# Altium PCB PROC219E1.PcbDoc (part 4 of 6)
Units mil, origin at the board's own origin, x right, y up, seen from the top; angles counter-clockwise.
Board outline 5354.33 x 5354.33 mil, 4 copper layers (Top Layer, Inner Layer 1, Inner Layer 2, Bottom Layer), stack 62.449 mil thick; 579 components, 299 nets, 1709 pads, 802 vias.
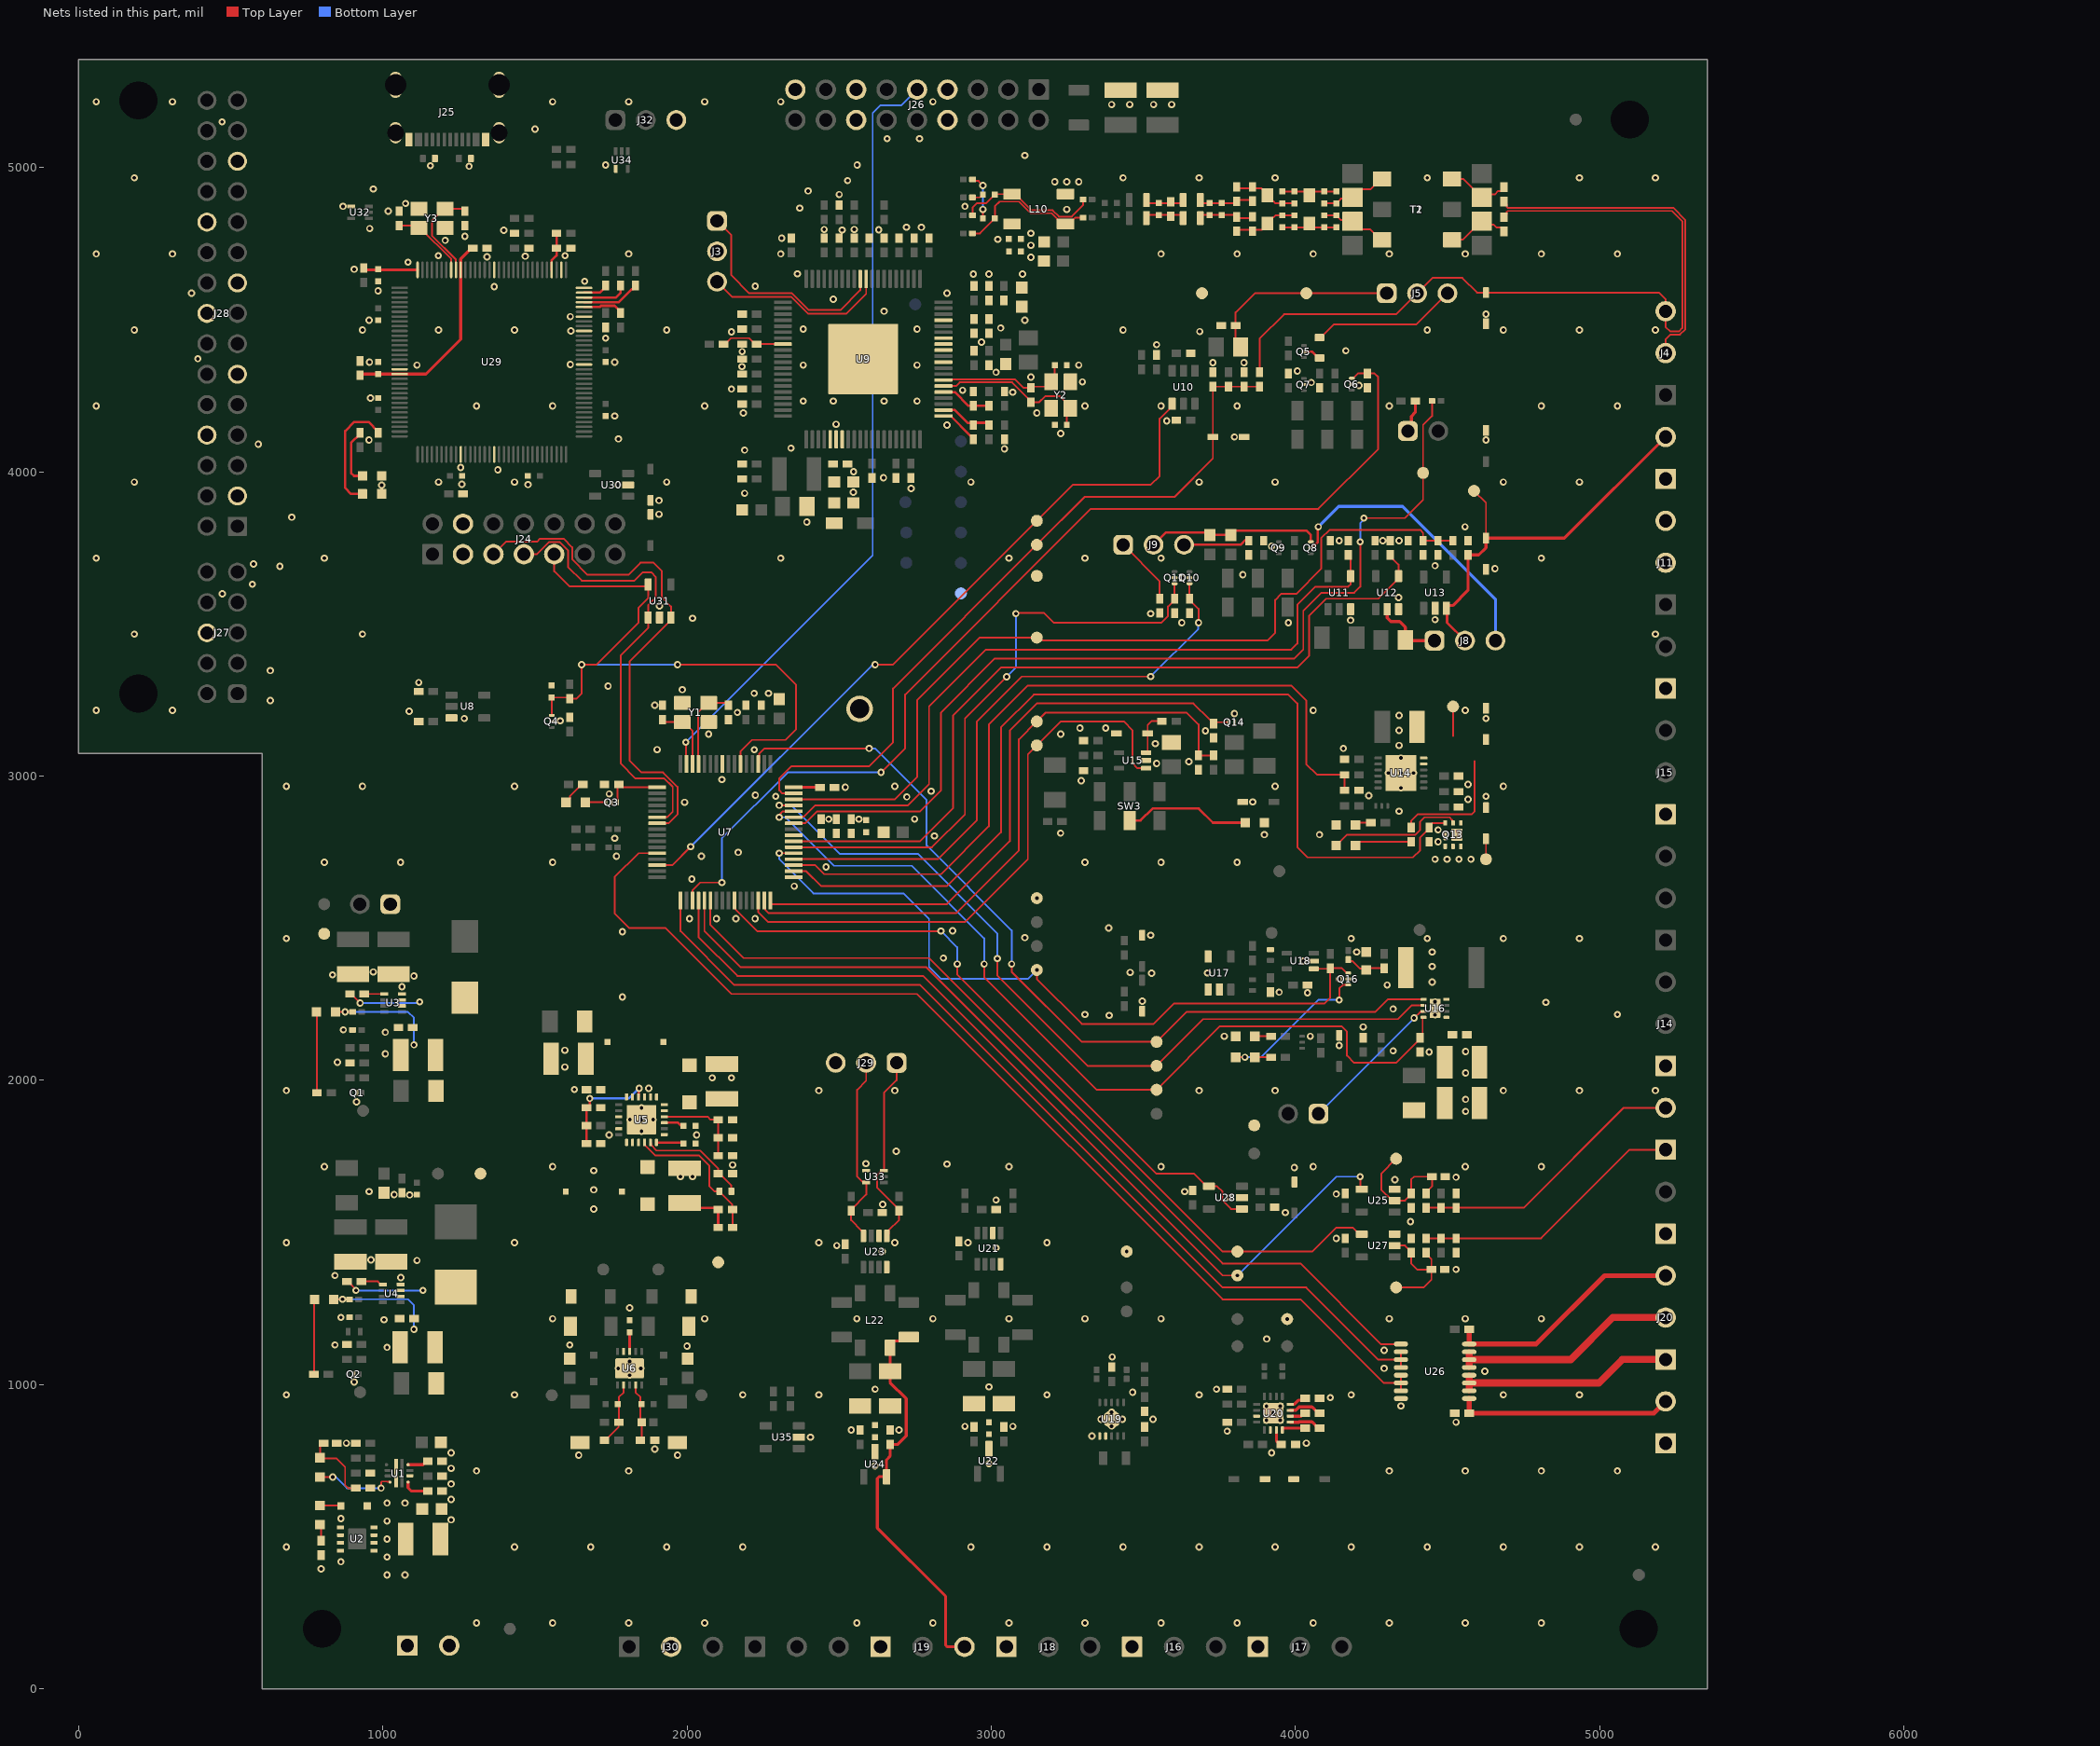
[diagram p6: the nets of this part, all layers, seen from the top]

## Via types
v1: diameter 23.62, hole 11.81, Top Layer to Bottom Layer, tented both sides, 802 vias

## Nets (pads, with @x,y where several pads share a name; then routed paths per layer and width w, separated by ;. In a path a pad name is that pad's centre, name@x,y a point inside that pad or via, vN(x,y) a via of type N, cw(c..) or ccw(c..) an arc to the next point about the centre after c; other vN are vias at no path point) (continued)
CAN2_P: C141.1 J19.3 L22.4 R139.2 R142.2 U24.2 | length 1306.5
  Top Layer w9.84: R139.2@2728.35,1155.51 2715.55,1142.72 2680.12,1142.72 2667.32,1129.92 L22.4@2667.32,1121.06 R142.2@2667.32,1043.31 2667.32,1006.43 2720.47,953.28 2720.47,830.71 2692.91,803.15 C141.1@2667.32,803.15 2667.32,764.27 2655.51,752.46 U24.2@2655.51,696.85 2630.8,696.85 2625.03,691.08 2625.03,528.54 2849.83,303.73 2849.83,143.56 2855.6,137.8 J19.3@2911.81,137.8
CAN2_RX: J29.2 R141.1 U23.4 U33.5 | length 637.1
  Top Layer w5.91: U23.4@2579.72,1488.19 2579.72,1500 2573.82,1505.91 2573.27,1505.91 2539.37,1539.81 2539.37,1574.8 2588.98,1624.41 U33.5@2588.98,1663.39 2586.02,1666.34 2575.79,1666.34 2559.06,1683.07 2559.06,1968.5 2588.58,1998.03 J29.2@2588.58,2057.09
CAN2_TX: J29.1 R140.1 U23.1 U33.3 | length 647.1
  Top Layer w5.91: U23.1@2656.5,1488.19 2662.4,1494.09 2662.4,1506.17 2696.85,1540.62 2696.85,1574.8 2624.31,1647.34 2624.31,1688.07 2636.04,1699.8 2644.29,1699.8 U33.3@2647.24,1702.76 2647.24,1958.27 2688.5,1999.52 2688.5,2057 J29.1@2688.58,2057.09
ChargeSeq1: D19.2 J11.3 R96.1 TP25.1 U14.5 U14.6 | length 505.2
  Top Layer w5.91: R96.1@4379.92,2830.71 4379.92,2852.36 4401.57,2874.02 4578.74,2874.02 4588.58,2883.86 4588.58,3049.21 ; 4517.72,3131.89 TP25.1@4517.72,3228.35
ChargeSeq2: D21.2 D22.1 J11.2 Q13.1 Q13.2 Q13.5 Q13.6 Q13.8 TP26.1 | length 517
  Top Layer w5.91: D22.1@4133.86,2771.65 4168.62,2806.41 4393.02,2806.41 4409.45,2822.84 4409.45,2850.39 4423.17,2864.11 4505.97,2864.11 4514.76,2855.31 4514.76,2848.43 Q13.2@4517.72,2845.47 ; TP26.1@4625.98,2726.38 D21.2@4625.98,2793.31
CP_EV: D17.2 J5.3 | length 481.2
  Top Layer w5.91: D17.2@4078.74,4440.94 4082.68,4440.94 4125.98,4484.25 4397.24,4484.25 J5.3@4499.61,4586.61
CP_N: C97.1 J4.2 NT1.2 | length 1112.7
  Top Layer w5.91: C97.1@4685.04,4887.8 4693.9,4878.94 4693.9,4870.62 4697.36,4867.16 5241.34,4867.16 5281.56,4826.94 5281.56,4468.34 5263.95,4450.72 5232.28,4450.72 5216.54,4434.98 J4.2@5216.54,4386.32
CP_P: C107.1 D14.2 J4.3 J5.2 R63.2 | length 2678.4
  Top Layer w5.91: R63.2@3881.89,4326.77 3881.89,4437.01 3962.6,4517.72 4330.71,4517.72 J5.2@4399.61,4586.61 4449.8,4636.81 4548.23,4636.81 4596.46,4588.58 D14.2@4625.98,4588.58 5194.88,4588.58 5216.54,4566.93 5216.54,4524.11 5216.54,4476.38 5232.28,4460.63 5259.84,4460.63 5271.65,4472.44 5271.65,4822.83 5237.24,4857.25 4697.36,4857.25 4693.9,4853.79 4693.9,4845.47 C107.1@4685.04,4836.61
DEBUG_ID4: R154.1 U29.63 | length 83
  Top Layer w7.87: U29.63@1661.42,4588.58 1712.6,4588.58 1732.28,4608.27 R154.1@1732.28,4612.2
DEBUG_ID5: R155.1 U29.62 | length 150.7
  Top Layer w7.87: U29.62@1661.42,4572.83 1766.5,4572.83 1781.5,4587.83 R155.1@1781.5,4612.2
DEBUG_ID6: R156.1 U29.61 | length 194.4
  Top Layer w7.87: U29.61@1661.42,4557.09 1712.14,4557.09 1712.27,4557.21 1775.72,4557.21 1818.9,4600.39 1822.83,4600.39 1830.71,4608.27 R156.1@1830.71,4612.2
DEBUG_ID7: R157.1 U29.60 | length 133.9
  Top Layer w7.87: U29.60@1661.42,4541.34 1713.18,4541.34 1717.18,4545.34 1761.75,4545.34 1781.5,4525.59 R157.1@1781.5,4521.65
DIG_IN_1: J21.2 R145.2 R146.1 R147.2 | length 923.6
  Top Layer w5.91: R146.1@4429.13,1580.71 R145.2@4478.35,1580.71 R147.2@4527.56,1580.71 4750,1580.71 5078.74,1909.45 J21.2@5216.54,1909.45
DIG_IN_2: J21.1 R149.2 R150.1 R151.2 | length 908.1
  Top Layer w5.91: R150.1@4429.13,1480.31 R151.2@4527.56,1480.32 4807.09,1480.32 5097.93,1771.16 5216.04,1771.16 J21.1@5216.54,1771.65
DIG_OUT_1: J20.3 R148.1 U26.16 | length 787.1
  Top Layer w15.75: R148.1@4570.87,1181.1 U26.16@4570.87,1132.87 4791.05,1132.87 5015.96,1357.78 J20.3@5216.54,1357.78
DIG_OUT_2: J20.2 U26.13 U26.14 U26.15 | length 746.3
  Top Layer w23.62: U26.13@4570.87,1060.04 U26.14@4570.87,1081.69 ; U26.15@4570.87,1103.35 U26.14@4570.87,1081.69 ; J20.2@5216.54,1219.98 5042.81,1219.98 4904.53,1081.69 U26.14@4570.87,1081.69
DIG_OUT_3: J20.1 U26.10 U26.11 U26.12 | length 721
  Top Layer w23.62: U26.10@4570.87,983.27 U26.11@4570.87,1004.92 ; U26.12@4570.87,1026.57 U26.11@4570.87,1004.92 ; J20.1@5216.54,1082.18 5074.31,1082.18 4997.05,1004.92 U26.11@4570.87,1004.92
DIG_OUT_COM: C145.1 J23.2 U26.9 | length 710.5
  Top Layer w15.75: U26.9@4571.24,953.36 U26.9@4570.87,953.74 C145.1@4570.87,905.51 5177.66,905.51 J23.2@5216.54,944.39
EN_RSTD: R43.1 R48.2 U9.8 | length 211.2
  Top Layer w5.91: R43.1@2120.08,4419.29 2124.02,4419.29 2143.7,4438.98 2204.72,4438.98 2224.41,4419.29 R48.2@2228.35,4419.29 U9.8@2314.96,4419.29
GBT_CC1: D18.1 J7.2 J8.2 R77.1 TP23.1 U13.3 | length 1343.2
  Top Layer w5.91: TP23.1@4586.61,3937.01 4625.98,3897.64 D18.1@4625.98,3781.5
  Top Layer w7.87: U13.3@4502.95,3560.18 4498.03,3555.26 4498.03,3503.94 J8.2@4557.09,3444.88
  Top Layer w9.84: U13.3@4502.95,3560.18 4516.87,3560.18 4566.93,3610.24 R77.1@4566.93,3726.38 4602.36,3726.38 4625.98,3750 D18.1@4625.98,3781.5 4883.86,3781.5 J7.2@5216.54,4114.17
GBT_EV: J8.3 Q8.2@4050.42,3750 | length 954.2
  Top Layer w7.87: Q8.2@4050.42,3750 4055.15,3750 4073.38,3768.23 4073.38,3817.47 v1(4074.8,3818.9)
  Bottom Layer w9.84: v1(4074.8,3818.9) 4141.73,3885.83 4352.36,3885.83 4657.09,3581.1 J8.3@4657.09,3444.88
GND: C1.2 C2.1 C3.1 C4.1 C5.2 C6.2 C7.2 C9.1 C10.2 C11.1 C12.1 C14.1 C15.2 C16.1 C17.1 C18.2 C19.2 C20.2 C21.1 C22.2 C25.1 C26.2 C27.1 C28.1 C29.2 C31.2 C32.2 C33.2 C34.2 C35.1 C37.1 C38.1 C39.2 C40.2 C41.2 C42.2 C43.1 C44.2 C45.1 C46.2 C47.2 C48.1 C49.2 C50.2 C51.2 C54.1 C55.2 C56.2 C57.2 C58.2 C59.1 C60.2 C61.2 C62.2 C63.2 C64.2 C65.2 C66.2 C67.2 C68.2 C69.2 C70.2 C71.2 C72.2 C73.2 C74.2 C75.2 C76.2 C77.2 C78.2 C79.2 C80.2 C81.2 C82.2 C83.2 C84.2 C86.2 C87.2 C88.1 C89.1 C90.1 C91.2 C92.1 C93.1 C114.1 C115.1 C116.2 C117.1 C118.2 C119.1 C120.2 C121.1 C122.1 C123.2 C124.1 C125.2 C126.1 C127.2 C128.2 C129.2 C132.2 C133.2 C134.2 C135.2 C136.2 C137.2 C138.1 C139.2 C140.2 C141.2 C142.2 C143.1 C144.1 C145.2 C146.1 C147.2 C148.2 C149.2 C150.1 C151.1 C152.1 C153.1 C154.1 C155.1 C156.2 C157.2 C158.1 C159.2 C160.1 C161.2 C162.1 C163.2 C164.2 D1.2 D14.1 D15.2 D16.2 D18.2 D19.1 D20.1 D21.1 D23.1 D24.2 D25.1 D26.2 D27.1 D29.2 D30.2 D31.1 D32.1 D33.2 D34.2 D35.2 D36.2 D37.2 D38.1 D39.1 J1.2 J2.1 J3.2 J7.1 J10.1 J14.1 J15.1 J16.1 J17.1 J18.1 J19.1 J22.1 J23.1 J24.3 J24.4 J25.1 J25.2 J25.3 J25.4 J25.A1-B12 J25.B1-A12 J26.7 J26.8 J26.13 J26.14 J26.17 J27.6 J28.3 J28.8 J28.11 J28.16 J28.17 J28.22 J28.25 J29.3 J30.2 J32.3 L8.2 NT1.1 Q1.2@915.35,1958.66 Q2.2@905.51,1033.46 Q3.2@1751.97,2913.39 Q4.2@1555.12,3179.13 Q6.2@4185.04,4287.4 Q7.2@4027.56,4286.42 Q9.2@3944.88,3750 Q10.2@3651.57,3651.57 Q11.2@3602.36,3651.57 Q13.4 Q13.7 Q14.2@3799.21,3176.68 Q16.2@4173.23,2332.68 R5.1 R6.1 R7.2 R11.2 R12.1 R17.2 R18.1 R22.2 R23.2 R30.1 R36.2 R38.1 R39.1 R40.2 R47.1 R48.1 R49.1 R50.1 R59.1 R62.1 R65.1 R68.1 R71.2 R72.2 R75.1 R76.1 R77.2 R79.1 R83.1 R84.1 R85.2 R86.2 R87.2 R89.1 R90.2 R92.1 R93.1 R95.1 R100.1 R101.2 R105.1 R106.1 R110.2 R112.2 R115.1 R116.2 R127.1 R132.2 R147.1 R151.1 R153.1 R162.1 R163.1 R165.1 R166.1 TP18.1 TP37.1 TP38.1 TP41.1 TP44.1 TP45.1 TP49.1 TP50.1 TP51.1 TP52.1 TP58.1 U1.8 U2.5 U2.6 U2.7 U2.8 U3.4 U4.4 U5.2 U5.3 U5.9 U5.11 U5.19 U5.25@1850.24,1870.27 U6.4 U6.11 U7.17 U7.41 U8.3 U9.54 U9.81 U11.3 U12.3 U13.2 U14.13 U15.2 U16.4 U16.9 U17.1 U17.2 U17.5 U18.2 U19.6 U19.7 U19.11 U20.11 U20.14 U20.17 U21.2 U21.8 U22.3 U23.2 U23.8 U24.3 U25.3 U26.8 U27.3 U28.2 U29.10 U29.17 U29.48 U29.55 U29.58 U29.64 U29.66 U29.80 U29.114 U30.2 U31.2 U32.4 U33.4 U34.4 U35.2 Y1.2 Y1.4 Y2.2 Y2.4 Y3.2 Y3.4
  other v1: 1308,216 1558,216 1808,216 2058,216 2558,216 2808,216 3058,216 3308,216 3558,216 3808,216 4058,216 4308,216 4558,216 4808,216 797.24,393.7 862.2,417.32 683,466 1433,466 1683,466 1933,466 2183,466 2933,466 3183,466 3433,466 3683,466 3933,466 4183,466 4433,466 4683,466 4933,466 5183,466 1224.41,555.12 862.2,559.06 1224.41,622.05 1224.41,673.23 1308,716 1808,716 4308,716 4558,716 4808,716 5058,716 1224.41,724.41 2618.11,732.28 2992.13,740.16 1643.7,767.72 1968.5,767.72 1224.41,775.59 3921.26,775.59 1893.7,787.4 880.11,807.1 4035.43,807.09 2405.51,826.77 3330.71,830.71 3775.59,846.46 2539.37,850.39 2696.85,850.39 2913.39,862.2 3070.87,862.2 3395.67,863.19 4527.56,875.98 3904.33,882.68 3950,882.68 3360.24,885.83 3431.1,885.83 3531.5,885.83 3927.17,905.51 3395.67,908.46 3904.33,928.35 3950,928.35 4346.46,929.13 4114.17,956.69 683,966 1433,966 2183,966 2433,966 3183,966 3683,966 4183,966 4683,966 4933,966 3464.57,974.41 2618.11,984.25 3740.16,984.25 2992.13,992.13 905.51,1007.87 1811.02,1030.51 4622.05,1043.31 1773.62,1053.15 1848.43,1053.15 4291.34,1053.15 1811.02,1075.79 3397.64,1090.55 4291.34,1112.2 1013.78,1122.05 2000,1125.98 842.52,1129.92 1614.17,1129.92 3905.51,1149.61 1003.94,1212.6 3972.44,1215.07 1558,1216 2058,1216 2558,1216 2808,1216 3058,1216 3308,1216 3558,1216 4308,1216 4558,1216 4808,1216 862.2,1220.47 1811.02,1251.97 1059.06,1351.38 842.52,1358.27 4527.56,1377.95 1112.2,1407.48 960.63,1409.45 2641.73,1437.01 3444.88,1437.01 3015.75,1448.82 2492.13,1456.69 683,1466 1433,1466 2433,1466 2683,1466 3183,1466 2923.23,1466.54 4133.86,1480.32 4377.95,1535.43 3966.54,1564.96 1692.91,1576.77 2642.88,1592.01 3015.75,1606.3 3783.46,1614.17 1088.32,1622.93 1036.98,1623.77 4133.86,1625.98 954.72,1633.86 3635.8,1634 1692.91,1639.76 4326.77,1673.23 4527.56,1681.1 1978.35,1683.07 2017.72,1683.07 1692.91,1702.76 3996.06,1712.6 808,1716 1558,1716 3058,1716 3558,1716 4058,1716 4558,1716 4808,1716 2149.45,1721.65 2854.33,1724.41 2587.66,1726.07 2687.19,1766.81 1743.94,1820.07 2031.34,1820.07 1850.24,1831.88 1811.85,1870.27 1850.24,1870.27 1888.63,1870.27 4559.06,1897.64 1850.24,1908.66 913.39,1929.13 4559.06,1937.01 683,1966 2433,1966 2683,1966 3683,1966 3933,1966 4683,1966 4933,1966 5183,1966 1629.77,1969.68 1873.86,1973.62 2082.68,2007.87 2145.67,2007.87 4559.06,2023.62 1598.43,2043.31 850.39,2059.06 1007.87,2086.61 4438.98,2092.52 4559.06,2094.49 4320.87,2096.46 1598.43,2098.43 4143.7,2114.27 3765.94,2144.47 4048.31,2144.47 1007.87,2157.48 870.08,2165.35 4222.44,2175.2 3387.8,2212.98 4458.66,2214.57 3308,2216 5058,2216 4320.87,2234.25 4822.83,2255.91 4458.66,2257.87 3496.06,2259.84 1787.3,2273.83 4039.37,2287.4 3946.22,2289.37 1062.99,2307.09 4301.18,2312.99 4448.82,2322.83 4143.7,2332.68 1102.36,2342.52 834.65,2346.46 3526.95,2351.74 3710.63,2352.36 3456.69,2354.33 968.81,2355.9 4448.82,2374.02 4025.59,2391.73 2842.52,2401.57 4200.79,2421.26 4448.82,2421.26 683,2466 4183,2466 4433,2466 4683,2466 4933,2466 3110.24,2468.5 3523.62,2476.38 1787.3,2488.19 2873.04,2490.99 3385.83,2500 2007.87,2530.85 2096.45,2530.85 2160.46,2530.85 2223.66,2530.85 3149.61,2598.43 2352.36,2637.8 2015.75,2661.42 2456.69,2700.79 808,2716 1058,2716 1558,2716 3308,2716 3558,2716 3808,2716 4458.66,2726.38 4498.03,2726.38 4537.4,2726.38 4576.77,2726.38 1767.72,2736.22 2047.24,2736.22 2168.37,2748.8 4468.5,2783.46 1761.81,2795.28 2813.3,2802.81 3897.64,2807.09 4078.74,2807.09 3227.81,2812.26 4468.5,2822.83 2465.59,2858.01 2564.93,2858.01 2748.03,2858.27 4340.55,2883.86 1992.13,2913.39 3859.07,2914.55 4566.93,2923.23 2722.09,2931.27 2291.34,2933.07 4625.98,2933.07 4240.63,2935.44 2224.41,2937.01 1744.09,2940.94 2802.13,2950 4346.46,2960.63 2519.89,2962.81 683,2966 933,2966 1433,2966 2683,2966 3933,2966 4683,2966 4566.93,2972.44 3295.28,2984.25 2114.17,2988.19 4305.12,3009.84 4346.46,3009.84 4387.8,3009.84 3543.31,3041.34 3649.61,3047.24 4346.46,3059.06 2220.87,3086.43 1901.57,3086.61 4157.48,3090.55 4340.55,3100.39 3539.37,3106.3 2070.87,3137.8 3228.35,3137.8 3703.84,3148.46 4340.55,3149.61 3291.34,3157.48 3376.11,3157.48 1582.68,3181.1 1267.72,3188.98 4625.98,3188.98 4340.55,3198.82 3799.21,3204.72 2165.35,3208.66 1086.61,3212.6 58,3216 308,3216 4058,3216 4558,3216 1893.7,3232.28 629.92,3248.03 2220.47,3271.65 2267.72,3271.65 1984.25,3283.46 1740.16,3295.28 1118.11,3307.09 629.92,3346.46 183,3466 933,3466 5183,3466 3625.98,3503.94 3976.38,3503.94 4181.1,3511.81 4458.66,3513.78 2018.09,3518.38 3523.62,3533.46 1909.45,3559.06 4338.58,3586.61 472.29,3598.71 570.87,3629.92 3626.97,3651.57 3826.77,3661.42 4655.51,3681.1 661.42,3688.98 4458.66,3690.94 574.8,3696.85 58,3716 808,3716 2308,3716 3058,3716 3308,3716 3558,3716 4808,3716 3921.1,3755 4143.7,3773.62 4286.45,3773.62 4340.55,3773.62 4557.09,3818.9 2393.7,3834.65 700.79,3850.39 1907.48,3860.24 1907.48,3905.51 2188.98,3929.13 2546.75,3932.58 2736.22,3944.88 996.1,3955.56 1771.65,3956.69 1477.37,3957.69 1259.84,3958.66 183,3966 1183,3966 1433,3966 1933,3966 2933,3966 3683,3966 3933,3966 4683,3966 4933,3966 2645.67,3980.31 2547.24,4000 1377.95,4005.91 1255.91,4013.59 2188.98,4070.87 3043.31,4074.8 2341.57,4077.2 590.55,4090.55 954.37,4104.01 4625.98,4104.33 1774.16,4107.71 3799.21,4114.17 3228.35,4125.98 2854.33,4153.54 2489.87,4155.98 3576.75,4167.07 1761.81,4183.07 2185.04,4192.91 3149.61,4192.91 58,4216 1308,4216 1558,4216 2058,4216 3308,4216 3558,4216 3808,4216 4308,4216 4808,4216 5058,4216 2381.89,4232.28 2480.32,4232.28 2647.64,4232.28 2755.91,4232.28 959.69,4241.97 3070.67,4261.15 2905.51,4267.72 2145.67,4271.65 4208.66,4283.46 4051.81,4293.17 3299.21,4295.28 3129.92,4311.02 3015.75,4326.77 4005.91,4330.71 2180.5,4345.44 1112.2,4350.39 2381.89,4350.39 2755.91,4350.39 3287.4,4350.39 1616.14,4352.36 3728.35,4358.27 3830.71,4358.27 955.78,4360.23 1761.81,4360.24 391.76,4371.16 2181.1,4394.89 4165.35,4397.64 3543.31,4417.32 2967.74,4426.17 1732.28,4438.98 2145.67,4459.57 3685.04,4460.63 1618.11,4462.6 183,4466 933,4466 1183,4466 1433,4466 1933,4466 3433,4466 4433,4466 4683,4466 4933,4466 5183,4466 2381.89,4468.5 2755.91,4468.5 3031,4472.35 954.73,4498.03 3110.24,4498.03 1616.14,4509.84 4625.98,4517.72 2647.64,4527.56 2480.32,4566.93 370.79,4587.06 2854.33,4586.61 984.25,4594.49 1366.14,4608.27 2224.05,4609.91 1663.39,4625.98 2362.84,4650.16 2940.94,4649.61 2992.13,4649.61 3102.36,4649.61 905.51,4665.35 1082.48,4688.49 1342.52,4706.2 1467.69,4708.14 1182.29,4710.28 1598.83,4710.18 58,4716 308,4716 1808,4716 2308,4716 3558,4716 3808,4716 4058,4716 4308,4716 4558,4716 4808,4716 5058,4716 1204.94,4760.24 3021.65,4763.78 2311.02,4767.72 1269.68,4773.62 1397.64,4793.31 2509.76,4794.45 2629.92,4795.28 2450.87,4796.18 2549.37,4796.18 956.69,4799.21 2721.17,4803.43 2769.95,4803.22 1017.72,4856.3 3248.03,4862.2 2370.08,4866.14 868.73,4872.18 2913.39,4872.05 1074.8,4881.89 2500,4911.18 2397.6,4922.68 968.84,4929.02 2527.56,4956.69 183,4966 3433,4966 3683,4966 3933,4966 4433,4966 4933,4966 5183,4966 1283.46,5003.94 1156.38,5005.64 1732.28,5007.87 2559.06,5007.87 3110.24,5039.37 2657.48,5094.49 2763.78,5094.49 1500,5125.98 471.29,5149.64 3395.67,5206.69 3454.72,5206.69 3533.46,5206.69 3592.52,5206.69 58,5216 308,5216 1558,5216 1808,5216 2058,5216 2308,5216 2808,5216
HFXIN: C43.2 U7.45 Y1.1 | length 286.6
  Top Layer w5.91: U7.45@2037.4,3039.37 2036.35,3040.42 2036.35,3210.57 2065.95,3240.16 Y1.1@2070.87,3240.16 2127.95,3240.16 C43.2@2135.83,3232.28
HFXOUT: C44.1 U7.46 Y1.3 | length 222.8
  Top Layer w5.91: C44.1@1919.29,3185.04 1927.17,3177.17 Y1.3@1984.25,3177.17 1989.17,3177.17 2017.72,3148.62 U7.46@2017.72,3039.37
MSP_ADC_CP: C93.2 D15.1 R63.1 R64.1 R65.2 TP21.1 U7.31 | length 2450.4
  Top Layer w5.91: U7.31@2350.39,2942.91 2312.99,2942.91 2303.15,2952.76 2303.15,2992.13 2342.52,3031.5 2598.43,3031.5 2677.17,3110.24 2677.17,3287.4 TP21.1@3149.61,3759.84 3307.09,3917.32 3602.36,3917.32 3728.35,4043.31 D15.1@3728.35,4114.17 C93.2@3728.35,4279.53 R64.1@3779.53,4279.53 R63.1@3881.89,4279.53 R63.1@3885.82,4283.46
MSP_ADC_GBT_DP1: C117.2 R78.1 R79.2 TP24.1 U7.30 | length 2841.9
  Top Layer w5.91: U7.30@2350.39,2923.23 2683.07,2923.23 2755.91,2996.06 2755.91,3248.03 2962.6,3454.72 3158.66,3454.72 3168.5,3444.88 3907.48,3444.88 3933.08,3470.48 3933.08,3578.75 3952.73,3598.4 4001.94,3598.4 4084.27,3680.72 4084.27,3781.11 4112.21,3809.06 4409.45,3809.06 4419.29,3799.21 C117.2@4419.29,3773.62 R79.2@4468.5,3773.62 R78.1@4517.72,3773.62
MSP_ADC_IN_3: U7.10 U28.1 U28.4 | length 2172.4
  Top Layer w5.91: U7.10@2155.51,2590.55 2158.46,2587.6 2158.46,2562.01 2230.31,2490.16 v1(2834.65,2490.16) ; v1(2887.8,2381.89) 2887.8,2348.43 3543.31,1692.91 3666.34,1692.91 3707.68,1651.57 3742.13,1651.57 3759.84,1633.86 3759.84,1604.33 3787.4,1576.77 U28.1@3823.82,1576.77
  Bottom Layer w5.91: v1(2834.65,2490.16) 2887.8,2437.01 v1(2887.8,2381.89)
MSP_ADC_PP: R67.2 TP22.1 U7.26 | length 3196.1
  Top Layer w5.91: U7.26@2350.39,2844.49 2387.8,2844.49 2427.17,2883.86 2765.75,2883.86 2834.65,2952.76 2834.65,3208.66 3011.81,3385.83 3996.06,3385.83 4025.59,3415.35 4025.59,3543.31 4084.65,3602.36 4192.91,3602.36 4212.6,3622.05 v1(4212.6,3769.69) ; v1(4224.74,3847.59) 4359.4,3847.59 4419.29,3907.48 TP22.1@4419.29,3996.06 4419.29,4153.54 4448.72,4182.97 R67.2@4448.72,4232.28
  Bottom Layer w5.91: v1(4212.6,3769.69) 4212.6,3830.66 4224.74,3842.79 v1(4224.74,3847.59)
MSP_DEBUG_UART_RX: J24.5 U7.55 U31.3 | length 1728.1
  Top Layer w5.91: J24.5@1363.39,3728.74 1404.79,3770.14 1506.36,3770.14 1515.75,3779.53 1594.49,3779.53 1622.45,3751.57 1622.45,3712.2 1673.23,3661.42 1807.09,3661.42 1846.46,3700.79 1889.76,3700.79 1917.32,3673.23 1917.32,3586.61 1946.85,3557.09 U31.3@1946.85,3520.67 1937.99,3511.81 1937.99,3503.33 1811.02,3376.37 1811.02,3051.18 1850.39,3011.81 1920.99,3011.81 1968.5,2964.3 1968.5,2874.02 1938.98,2844.49 U7.55@1901.57,2844.49
MSP_DEBUG_UART_TX: J24.7 U7.54 U31.1 | length 1557.8
  Top Layer w5.91: J24.7@1463.39,3728.74 1506.23,3728.74 1546.64,3769.16 1580.13,3769.16 1609.47,3739.82 1609.47,3685.81 1653.54,3641.73 1826.77,3641.73 1854.33,3669.29 1881.89,3669.29 1897.52,3653.66 1897.52,3586.5 1872.05,3561.02 U31.1@1872.05,3520.67 1872.05,3486.22 1781.5,3395.67 1781.5,3041.34 1830.82,2992.02 1925.2,2992.02 1952.76,2964.46 1952.76,2881.89 1935.81,2864.94 1902.35,2864.94 U7.54@1901.57,2864.17
MSP_GPIO_CdM_d1: R88.1 R90.1 U7.19 | length 2571
  Top Layer w5.91: U7.19@2350.39,2706.69 2421.26,2706.69 2450.79,2677.17 2834.65,2677.17 2992.13,2834.65 2992.13,3169.29 3120.08,3297.24 3986.22,3297.24 4035.43,3248.03 4035.43,3039.37 4070.87,3003.94 R88.1@4161.42,3003.94 R90.1@4161.42,2952.76
MSP_GPIO_CdM_d2: Q13.3 R95.2 U7.18 | length 3199.4
  Top Layer w5.91: U7.18@2350.39,2687.01 2391.73,2687.01 2440.94,2637.8 2854.33,2637.8 3031.5,2814.96 3031.5,3159.45 3139.76,3267.72 3976.38,3267.72 4005.91,3238.19 4005.91,2765.75 4039.37,2732.28 4385.83,2732.28 4409.45,2755.91 4409.45,2797.86 4429.51,2817.91 4430.12,2817.91 4438.98,2826.77 4438.98,2834.65 4449.8,2845.47 Q13.3@4492.13,2845.47
MSP_GPIO_CdM_EV_CP: Q14.1@3779.53,3176.68 R101.1 U7.16 | length 2033.8
  Top Layer w5.91: U7.16@2273.62,2590.55 2273.62,2581.69 2276.57,2578.74 2854.33,2578.74 3061.02,2785.43 3061.02,3149.61 3149.61,3238.19 3664.55,3238.19 3717.52,3185.22 3721.46,3185.22 3730.31,3176.36 R101.1@3730.31,3172.43 3734.57,3176.68 Q14.1@3779.53,3176.68
MSP_GPIO_CdM_j: R99.2 R100.2 TP27.1 U7.15 | length 2113.7
  Top Layer w5.91: U7.15@2253.94,2590.55 2256.89,2587.6 2256.89,2560.6 2268.28,2549.21 2883.86,2549.21 3090.55,2755.91 3090.55,3120.08 TP27.1@3149.61,3179.13 3179.13,3208.66 3641.73,3208.66 3681.1,3169.29 R100.2@3681.1,3067.69 R99.2@3730.31,3067.69
MSP_GPIO_CdM_PD: TP28.1 U7.14 U15.1 | length 1928.4
  Top Layer w5.91: U7.14@2234.25,2590.55 2234.25,2552.17 2266.73,2519.68 2913.39,2519.68 3120.08,2726.38 3120.08,3070.87 TP28.1@3149.61,3100.39 3228.35,3179.13 3435.04,3179.13 3464.57,3149.61 3464.57,3041.34 3480.31,3025.59 U15.1@3508.86,3025.59
MSP_GPIO_EV_Charge: Q6.1@4185.04,4307.09 R71.1 U7.3 | length 3411.7
  Top Layer w5.91: U7.3@2017.72,2590.55 2018.49,2591.32 2018.49,2624.79 2043.31,2649.61 v1(2114.17,2649.61) ; v1(2637.8,3011.81) 2716.54,3090.55 2716.54,3267.72 3326.77,3877.95 4074.8,3877.95 4271.65,4074.8 4271.65,4311.02 4259.84,4322.83 R71.1@4236.22,4322.83 4205.51,4322.83 4189.76,4307.09 Q6.1@4185.04,4307.09
  Bottom Layer w5.91: v1(2114.17,2649.61) 2114.17,2795.28 2330.71,3011.81 v1(2637.8,3011.81)
MSP_GPIO_GBT_EV_S2: Q10.1@3651.57,3631.89 R86.1 U7.20 | length 1994.8
  Top Layer w5.91: U7.20@2350.39,2726.38 2824.8,2726.38 2952.76,2854.33 2952.76,3179.13 3100.39,3326.77 v1(3523.62,3326.77) ; Q10.1@3651.57,3631.89 3651.57,3578.74 3681.1,3549.21 v1(3681.1,3503.94)
  Bottom Layer w5.91: v1(3523.62,3326.77) 3680.12,3483.27 3680.12,3502.95 v1(3681.1,3503.94)
MSP_GPIO_GBT_EV_S2': Q11.1@3602.36,3631.89 R85.1 U7.22 | length 1974.8
  Top Layer w5.91: U7.22@2350.39,2765.75 2805.12,2765.75 2913.39,2874.02 2913.39,3188.98 v1@3050.1,3325.69 ; v1@3050.18,3325.6 v1(3050.18,3325.77) ; v1(3080.71,3533.46) 3082.68,3535.43 3173.23,3535.43 3204.72,3503.94 3559.12,3503.94 3580.82,3525.64 3580.82,3557.2 3602.36,3578.74 R85.1@3602.36,3582.68 Q11.1@3602.36,3631.89
  Bottom Layer w5.91: v1(3050.18,3325.77) 3080.71,3356.3 v1(3080.71,3533.46)
MSP_GPIO_GBT_S0: R75.2 U7.27 U11.4 | length 2472.5
  Top Layer w5.91: U7.27@2350.39,2864.17 2352.15,2865.93 2383.65,2865.93 2421.26,2903.54 2726.38,2903.54 2795.28,2972.44 2795.28,3228.35 2982.28,3415.35 3986.22,3415.35 4005.91,3435.04 4005.91,3562.99 4064.96,3622.05 4173.23,3622.05 4181.1,3629.92 U11.4@4181.1,3656.5 4181.1,3718.5 R75.2@4173.23,3726.38
MSP_GPIO_GBT_S1: R76.2 U7.23 U12.4 | length 2690.8
  Top Layer w5.91: U7.23@2350.39,2785.43 2765.75,2785.43 2874.02,2893.7 2874.02,3198.82 3031.5,3356.3 4005.91,3356.3 4045.28,3395.67 4045.28,3527.36 4100.6,3582.68 4272.64,3582.68 4338.58,3648.62 U12.4@4338.58,3656.5 4338.58,3694.88 4311.02,3722.44 R76.2@4311.02,3726.38
MSP_GPIO_PL_CdM_FB: Q16.1@4173.23,2352.36 R119.2 TP35.1 U7.21 U18.1 | length 2489.1
  Top Layer w5.91: v1(2303.15,2746.06) U7.21@2350.39,2746.06 ; v1(3149.61,2362.2) 3149.61,2332.68 3297.24,2185.04 3533.46,2185.04 3600.39,2251.97 4094.49,2251.97 4114.17,2271.65 R119.2@4114.17,2368.11 ; U18.1@4060.04,2366.14 4112.2,2366.14 R119.2@4114.17,2368.11 ; Q16.1@4173.23,2352.36 4168.5,2352.36 4152.76,2368.11 R119.2@4114.17,2368.11
  Bottom Layer w5.91: v1(2303.15,2746.06) 2303.15,2726.38 2415.35,2614.17 2710.63,2614.17 2795.28,2529.53 2795.28,2372.05 2834.65,2332.68 3120.08,2332.68 v1(3149.61,2362.2)
MSP_GPIO_PL_DIR: TP33.1 U7.29 U16.6 | length 2683.1
  Top Layer w5.91: v1(2303.15,2903.54) U7.29@2350.39,2903.54 ; v1(3019.69,2400.13) 3019.69,2344.49 3316.93,2047.24 TP33.1@3543.31,2047.24 3696.85,2200.79 4336.61,2200.79 4381.89,2246.06 U16.6@4421.26,2246.06
  Bottom Layer w5.91: v1(2303.15,2903.54) 2342.52,2903.54 2501.97,2744.09 2757.87,2744.09 3019.69,2482.28 v1(3019.69,2400.13)
MSP_GPIO_PL_nSLEEP: R110.1 TP31.1 U7.28 U16.8 | length 2903.8
  Top Layer w5.91: v1(2303.15,2864.17) 2306.54,2867.56 2306.54,2875.6 2314.79,2883.86 U7.28@2350.39,2883.86 ; v1(2976.38,2381.89) 2976.38,2338.58 3346.46,1968.5 TP31.1@3543.31,1968.5 3751.97,2177.17 4151.39,2177.17 4169.06,2159.5 4169.06,2080.94 4192.91,2057.09 4330.71,2057.09 4409.45,2135.83 R110.1@4409.45,2139.76 4417.74,2148.05 4417.74,2204.72 4419.7,2206.69 U16.8@4421.26,2206.69
  Bottom Layer w5.91: v1(2303.15,2864.17) 2322.83,2864.17 2482.28,2704.72 2738.19,2704.72 2976.38,2466.54 v1(2976.38,2381.89)
MSP_IO_IN_1: TP54.1 U7.4 U25.4 | length 2933.9
  Top Layer w5.91: U7.4@2037.4,2590.55 2037.4,2470.47 2165.35,2342.52 2775.59,2342.52 3759.84,1358.27 v1(3809.06,1358.27) ; v1(4212.6,1683.07) 4212.6,1646.65 U25.4@4217.52,1641.73
  Bottom Layer w5.91: v1(3809.06,1358.27) 4133.86,1683.07 v1(4212.6,1683.07)
MSP_IO_IN_2: TP56.1 U7.6 U27.4 | length 2707.8
  Top Layer w5.91: U7.6@2076.77,2590.55 2076.33,2590.11 2076.33,2510.28 2185.04,2401.57 2795.28,2401.57 3759.84,1437.01 TP56.1@3809.06,1437.01 4055.12,1437.01 4133.86,1515.75 4187.99,1515.75 4209.65,1494.09 U27.4@4217.52,1494.09
MSP_IO_OUT_1: U7.5 U26.1 | length 2952
  Top Layer w5.91: U7.5@2057.09,2590.55 2057.09,2490.16 2175.2,2372.05 2785.43,2372.05 3759.84,1397.64 4015.75,1397.64 4280.51,1132.87 U26.1@4346.46,1132.87
MSP_IO_OUT_2: U7.1 U26.2 U26.3 U26.4 | length 3103.1
  Top Layer w5.91: U7.1@1978.35,2590.55 1978.35,2490.16 2155.51,2312.99 2765.75,2312.99 3759.84,1318.9 4035.43,1318.9 4272.64,1081.69 U26.3@4346.46,1081.69 ; U26.4@4346.46,1056.1 U26.3@4346.46,1081.69 ; U26.2@4346.46,1107.28 U26.3@4346.46,1081.69
MSP_IO_OUT_3: U7.60 U26.5 U26.6 U26.7 | length 3566
  Top Layer w5.91: U7.60@1901.57,2746.06 1840.55,2746.06 1761.81,2667.32 1761.81,2549.21 1811.02,2500 1929.13,2500 2145.67,2283.46 2755.91,2283.46 3759.84,1279.53 4015.75,1279.53 4290.35,1004.92 U26.6@4346.46,1004.92 ; U26.7@4346.46,979.33 U26.6@4346.46,1004.92 ; U26.5@4346.46,1030.51 U26.6@4346.46,1004.92
MSP_LED: Q3.1@1771.65,2913.39 R36.1 U7.49 | length 190.7
  Top Layer w5.91: Q3.1@1771.65,2913.39 1771.65,2968.5 R36.1@1775.59,2972.44 1779.53,2972.44 1789.37,2962.6 U7.49@1901.57,2962.6
MSP_PWM_CP: TP20.1 U7.62 U10.4 | length 2435.9
  Top Layer w5.91: U7.62@1901.57,2706.69 1950.79,2706.69 v1(2011.81,2767.72) ; v1(2618.11,3366.14) 2677.17,3366.14 TP20.1@3149.61,3838.58 3267.72,3956.69 3523.62,3956.69 3553.15,3986.22 3553.15,4174.21 3594.49,4215.55 U10.4@3594.49,4223.43
  Bottom Layer w5.91: v1(2011.81,2767.72) 2606.85,3362.75 2614.72,3362.75 v1(2618.11,3366.14)
MSP_PWM_PL_EN: TP32.1 U7.35 U16.5 | length 2850.8
  Top Layer w5.91: U7.35@2234.25,3039.37 2236.39,3041.51 2236.39,3072.24 2254.71,3090.55 v1(2598.43,3090.55) ; v1(3066.93,2381.89) 3066.93,2356.3 3297.24,2125.98 TP32.1@3543.31,2125.98 3641.73,2224.41 4261.81,2224.41 4303.15,2265.75 U16.5@4421.26,2265.75
  Bottom Layer w5.91: v1(2598.43,3090.55) 2618.11,3090.55 2787.4,2921.26 2787.4,2771.65 3066.93,2492.13 v1(3066.93,2381.89)
MSP_PWM_R_ENABLE: J26.9 U7.47 | length 2572.7
  Top Layer w5.91: v1(1995.79,3110.94) 1996.91,3109.82 1996.91,3040.49 U7.47@1998.03,3039.37
  Bottom Layer w5.91: v1(1995.79,3110.94) 2610.05,3725.21 2610.05,5178.95 2635.6,5204.49 2704.49,5204.49 J26.9@2755.91,5255.91
MSP_R\S\T\: C49.1 J24.9 Q4.3@1555.12,3198.82 R37.1 U7.38 U31.5 | length 2158.9
  Top Layer w5.91: Q4.3@1555.12,3198.82 C49.1@1555.12,3257.87 1610.24,3257.87 R37.1@1614.17,3253.94 1635.83,3253.94 1653.54,3271.65 v1(1653.54,3366.14) 1702.76,3366.14 1840.55,3503.94 1840.55,3553.15 1872.05,3584.65 U31.5@1872.05,3628.94 ; J24.9@1563.39,3728.74 1563.39,3672.83 1612.72,3623.5 U31.5@1870.08,3623.5 ; v1(1968.5,3366.14) 2291.34,3366.14 2358.35,3299.13 2358.35,3153.62 2323.25,3118.52 2213.01,3118.52 2175.2,3080.71 U7.38@2175.2,3039.37
  Bottom Layer w5.91: v1(1653.54,3366.14) v1(1968.5,3366.14)
NetC4_2: C4.2 C5.1 D3.1 J1.1 R1.2 R2.2 U1.5 U2.1 U2.2 U2.3 U2.4
  other v1: 1013.78,374.02 1072.83,374.02 1013.78,433.07 1013.78,492.13 1013.78,551.18 1013.78,610.24 1072.83,610.24
NetC6_1: C6.1 U1.10 | length 69.9
  Top Layer w9.84: U1.10@1082.68,736.22 1131.89,736.22 1143.7,748.03 C6.1@1147.64,748.03
NetC7_1: C7.1 U1.7 | length 88.1
  Top Layer w9.84: U1.7@1082.68,679.13 1082.71,660.4 1093.5,649.61 C7.1@1147.64,649.61
NetC8_1: C8.1 U3.5 | length 65.4
  Top Layer w5.91: C8.1@938.98,2283.46 U3.5@1004.33,2283.46
NetC8_2: C8.2 L2.1 U3.3 | length 243.2
  Top Layer w5.91: C8.2@891.73,2283.46 895.67,2283.46 v1(925.2,2253.94)
  Bottom Layer w5.91: v1(925.2,2253.94) 1112.65,2253.94 1116.38,2257.67 v1(1121.17,2257.67)
NetC9_2: C9.2 C10.1 D5.2 L1.2 R8.2 U3.2 | length 379.2
  Top Layer w5.91: D5.2@844.49,2224.41 v1(875.98,2224.41) R8.2@900.54,2224.41
  Bottom Layer w5.91: v1(875.98,2224.41) 1054.73,2224.41 1054.81,2224.49 1071.18,2224.49 1071.26,2224.41 1082.68,2224.41 1102.36,2204.72 v1(1102.36,2116.14)
NetC13_1: C13.1 U4.5 | length 78.9
  Top Layer w5.91: C13.1@929.13,1338.58 983.27,1338.58 993.11,1328.74 U4.5@1003.94,1328.74
NetC13_2: C13.2 L5.1 U4.3 | length 264.5
  Top Layer w5.91: C13.2@881.89,1338.58 885.83,1338.58 911.42,1312.99 v1(911.42,1309.06)
  Bottom Layer w5.91: v1(911.42,1309.06) v1(1131.89,1309.06)
NetC14_2: C14.2 C15.1 D6.2 L3.2 R14.2 U4.2 | length 375.3
  Top Layer w5.91: D6.2@838.58,1279.53 839.21,1280.15 v1(867.21,1280.15) ; v1@866.59,1279.53 R14.2@890.7,1279.53
  Bottom Layer w5.91: v1(867.21,1280.15) 1082.05,1280.15 1102.36,1259.84 v1(1102.36,1181.1)
NetC21_2: C21.2 C23.1 D7.1 D8.2 R21.2 U5.23
NetC23_2: C23.2 R21.1 R22.1 U5.22 | length 299.4
  Top Layer w5.91: U5.22@1925.04,1880.11 2067.76,1880.11 2077.6,1870.27 C23.2@2102.21,1870.27 R21.1@2102.21,1811.22 R22.1@2102.21,1752.16
NetC24_1: C24.1 R20.1 R23.1 U6.9 | length 191.6
  Top Layer w5.91: U6.9@1830.71,998.03 1830.71,974.41 1846.46,958.66 1846.46,935.04 1846.46,880.77 R20.1@1851.24,875.98 1851.24,821.71 R23.1@1846.46,816.93
NetC27_2: C27.2 R24.2 U5.17 | length 357.1
  Top Layer w5.91: U5.17@1879.77,1795.47 1881.74,1793.5 1881.74,1786.49 1899.33,1768.89 2043.15,1768.89 2101.73,1710.31 2101.73,1693.58 C27.2@2102.21,1693.1 2106.15,1693.1 2145.21,1654.04 2145.21,1635.34 R24.2@2145.52,1635.03
NetC28_2: C28.2 C29.1 L6.1 L7.2 R26.2 U5.5 U5.6
NetC30_1: C30.1 C35.2 D10.1 D11.2 R25.2 U5.15 | length 180.6
  Top Layer w7.87: C35.2@1988.04,1592.71 2000.59,1580.16 2097.05,1580.16 C30.1@2102.21,1574.99 R25.2@2102.21,1515.94
NetC30_2: C30.2 R24.1 R25.1 U5.16 | length 494.4
  Top Layer w5.91: U5.16@1860.08,1795.47 1861.07,1794.48 1861.07,1787.02 1895.63,1752.46 2039.9,1752.46 2072.92,1719.44 2072.92,1652.51 2090.91,1634.53 2102.72,1634.53 R24.1@2104.18,1633.07 ; R25.1@2149.45,1515.94 C30.2@2149.45,1574.99 ; C30.2@2149.82,1574.99 2147.51,1577.3 2147.51,1592.2 2113.54,1626.18 2113.04,1626.18 R24.1@2106.15,1633.07 ; R24.1@2106.15,1633.07 R24.1@2106.15,1635.03 R24.1@2106.15,1633.07
NetC32_1: C32.1 U5.21 | length 63.1
  Top Layer w7.87: U5.21@1925.04,1860.43 1970.32,1860.43 1980.16,1850.59 C32.1@1984.1,1850.59
NetC33_1: C33.1 R26.1 R27.2 U5.4 | length 360.3
  Top Layer w7.87: C33.1@1669.14,1791.53 R27.2@1669.14,1850.59 R26.1@1669.14,1909.64 1672.42,1909.64 1680.3,1917.51 v1(1680.3,1939.97) ; U5.4@1840.4,1945.07 1841.38,1946.06 1841.38,1972.63 v1(1842.37,1973.62)
  Bottom Layer w7.87: v1(1680.3,1939.97) 1808.72,1939.97 v1(1842.37,1973.62)
NetC34_1: C34.1 U5.18 | length 86.3
  Top Layer w7.87: U5.18@1899.45,1795.47 1980.16,1795.47 C34.1@1984.1,1791.53
NetC36_1: C36.1 R28.1 R29.1 U6.7 | length 209.5
  Top Layer w5.91: R29.1@1728.35,816.93 1732.28,816.93 1775.14,859.78 1775.14,875.53 R28.1@1775.59,875.98 1775.59,935.04 1775.59,958.66 1791.34,974.41 U6.7@1791.34,998.03
NetC38_2: C38.2 U6.3 | length 59.1
  Top Layer w9.84: U6.3@1811.02,1108.27 C38.2@1811.02,1167.32
NetC42_1: C42.1 U7.32 | length 86.6
  Top Layer w9.84: U7.32@2350.39,2962.6 C42.1@2437.01,2962.6
NetC45_2: C45.2 C46.1 C47.1 C48.2 L9.2 U7.24
NetC50_1: C50.1 C51.1 L10.1 L10.3 R41.2 R46.2
  other v1: 3129.92,4704.72 3129.92,4744.09 3129.92,4783.46 3208.66,4952.76 3248.03,4952.76 3287.4,4952.76
NetC52_1: C52.1 L10.4 R51.1 R52.2 | length 469.7
  Top Layer w5.91: R51.1@2938.04,4783.46 2962.6,4783.46 C52.1@3011.81,4832.67 3011.81,4872.05 3027.48,4887.72 3090.4,4887.72 3128.68,4849.44 3197.87,4849.44 3218.01,4829.3 3218.01,4828.73 3232.77,4813.96 3254.43,4813.96 3275.97,4835.5 R52.2@3301.65,4835.5
NetC52_2: C52.2 R55.1 | length 150.8
  Top Layer w5.91: R55.1@2938.04,4960.63 2943.2,4955.47 2957.92,4955.47 v1(2972.44,4940.94) ; C52.2@2972.44,4832.67 v1(2972.44,4862.2)
  Bottom Layer w5.91: v1(2972.44,4862.2) v1(2972.44,4940.94)
NetC53_1: C53.1 L10.2 R53.1 R54.2 | length 471.6
  Top Layer w5.91: R53.1@2938.04,4842.52 2938.04,4867.18 2953.77,4882.91 2983.3,4882.91 C53.1@3011.81,4911.41 3012.78,4912.39 L10.2@3068.4,4912.39 3083.17,4897.62 3094.5,4897.62 3132.78,4859.34 3201.97,4859.34 3222.68,4838.63 3264.32,4838.63 3301.65,4875.96 R54.2@3301.65,4894.56
NetC53_2: C53.2 R56.1 | length 38.5
  Top Layer w5.91: R56.1@2938.04,4901.57 2962.6,4901.57 C53.2@2972.44,4911.41
NetC55_1: C55.1 C56.1 C57.1 C58.1 L12.1 U9.50 U9.52 U9.53 U9.57
NetC60_1: C60.1 C61.1 C62.1 FB1.1 U9.25 U9.26 U9.27
NetC67_1: C67.1 L14.1 U9.45 | length 168.4
  Top Layer w7.87: U9.45@2842.52,4261.81 2879.92,4261.81 2925.2,4216.54 C67.1@2940.94,4216.54 L14.1@2992.13,4216.54
NetC85_1: C85.1 U9.41 | length 132.5
  Top Layer w7.87: U9.41@2842.52,4183.07 2866.14,4183.07 2931.1,4118.11 2933.07,4118.11 2940.94,4110.24 C85.1@2940.94,4106.3
NetC85_2: C85.2 R58.1 U9.42 | length 176.1
  Top Layer w7.87: U9.42@2842.52,4202.76 2879.92,4202.76 2921.94,4160.74 2933.75,4160.74 C85.2@2940.94,4153.54 2948.29,4160.89 2984.78,4160.89 R58.1@2992.13,4153.54
NetC88_2: C88.2 R57.1 U9.46 Y2.1 | length 539.4
  Top Layer w5.91: U9.46@2842.52,4281.5 2883.86,4281.5 2896.37,4294 3068.2,4294 3129.92,4232.28 R57.1@3129.92,4228.35 3157.7,4228.35 3177.38,4248.03 3224.9,4248.03 3239.67,4233.27 3240.16,4233.27 3259.84,4213.58 Y2.1@3259.84,4208.66 3248.03,4196.85 C88.2@3248.03,4153.54
NetC89_2: C89.2 R57.2 U9.47 Y2.3 | length 435.4
  Top Layer w5.91: U9.47@2842.52,4301.18 2845.25,4303.91 3077.98,4303.91 3106.3,4275.59 R57.2@3129.92,4275.59 3133.86,4279.53 3181.1,4279.53 3208.66,4307.09 C89.2@3208.66,4350.39
NetC91_1: C91.1 J5.1 R61.2 TP19.1 | length 643.5
  Top Layer w5.91: R61.2@3819.53,4409.45 3803.15,4425.83 C91.1@3803.15,4480.31 3803.15,4523.62 3866.14,4586.61 J5.1@4299.61,4586.61
NetC94_1: C94.1 C95.1 C98.2 C99.1 L17.2 | length 213.6
  Top Layer w5.91: C98.2@3806.42,4931.47 3887.43,4931.47 3907.48,4911.42 L17.2@3907.48,4908.46 3907.48,4905.51 3924.21,4888.78 3927.17,4888.78 3934.05,4881.89 C95.1@3956.69,4881.89 C99.1@3996.06,4881.89
NetC94_2: C94.2 C98.1 C105.2 C106.2 L16.2 | length 182.5
  Top Layer w5.91: L16.2@3686.94,4892.78 3686.94,4891.21 3695.2,4882.94 C105.2@3717.84,4882.94 C106.2@3757.21,4882.94 3795.4,4882.94 3805.92,4893.47 3806.42,4893.47 3853.81,4893.47 C94.2@3858.27,4889.01
NetC95_2: C95.2 C96.1 C99.2 C100.1 L18.2 | length 177.2
  Top Layer w5.91: C95.2@3956.69,4921.26 C99.2@3996.06,4921.26 C96.1@4133.87,4921.26
NetC96_2: C96.2 C100.2 T1.1 T2.2 | length 224.4
  Top Layer w5.91: C100.2@4094.5,4881.89 C96.2@4133.87,4881.89 4149.11,4897.13 4186.5,4897.13 T2.2@4188.98,4899.61 ; T2.2@4187.01,4901.57 4213.66,4928.23 4245.55,4928.23 4279.53,4962.2 T1.1@4284.45,4962.2
NetC97_2: C97.2 T1.6 T2.7 | length 212.6
  Top Layer w5.91: T1.6@4514.76,4962.2 4551.57,4962.2 4581.69,4932.09 4581.69,4930.12 4610.24,4901.57 T2.7@4612.2,4901.57 4622.05,4911.42 4655.33,4911.42 4666.39,4922.48 4676.18,4922.48 4685.04,4931.34 C97.2@4685.04,4935.04
NetC103_1: C103.1 C104.1 L19.2 L20.1 | length 130.9
  Top Layer w5.91: L19.2@3509.77,4833.73 3509.77,4835.31 3518.04,4843.57 3589.88,4843.57 3622.37,4843.57 3630.64,4835.31 L20.1@3630.64,4833.73
NetC103_2: C103.2 C104.2 L15.2 L16.1 | length 130.9
  Top Layer w5.91: L15.2@3509.77,4892.78 3509.77,4891.21 3518.04,4882.94 3589.88,4882.94 3622.37,4882.94 3630.64,4891.21 L16.1@3630.64,4892.78
NetC105_1: C105.1 C106.1 C108.1 C111.2 L20.2 | length 182.7
  Top Layer w5.91: L20.2@3686.94,4833.73 3686.94,4835.3 3695.2,4843.57 C105.1@3717.84,4843.57 C106.1@3757.21,4843.57 3795.4,4843.57 3805.92,4833.05 3806.42,4833.05 3853.49,4833.05 C111.2@3858.27,4837.83
NetC107_2: C107.2 T1.4 T2.6 | length 211.7
  Top Layer w5.91: T1.4@4514.76,4762.2 4515.03,4762.47 4550.08,4762.47 4581.69,4794.08 4581.69,4794.29 4610.24,4822.83 T2.6@4612.2,4822.83 4622.49,4812.55 4651.07,4812.55 4661.45,4802.17 4676.18,4802.17 4685.04,4793.31 C107.2@4685.04,4789.37
NetC108_2: C108.2 C109.1 C111.1 C112.1 L17.1 | length 212.8
  Top Layer w5.91: C108.2@3806.42,4795.04 3889.53,4795.04 3907.48,4812.99 L17.1@3907.48,4815.94 3907.48,4818.9 3924.21,4835.63 3927.17,4835.63 3934.05,4842.52 C112.1@3956.7,4842.52 C109.1@3996.07,4842.52
NetC109_2: C109.2 C110.1 C112.2 C113.1 L18.1 | length 177.2
  Top Layer w5.91: C112.2@3956.7,4803.15 C109.2@3996.07,4803.15 C113.1@4133.86,4803.15
NetC110_2: C110.2 C113.2 T1.3 T2.3 | length 224.4
  Top Layer w5.91: C110.2@4094.48,4842.52 C113.2@4133.86,4842.52 4149.1,4827.28 4186.5,4827.28 T2.3@4188.98,4824.8 ; T2.3@4187.01,4822.83 4213.66,4796.18 4245.55,4796.18 4279.53,4762.2 T1.3@4284.45,4762.2
NetC121_2: C121.2 C122.2 C123.1 F1.1 U16.1
NetC126_2: C126.2 R117.1 R118.2 | length 134.8
  Top Layer w5.91: R118.2@4173.23,2396.6 4178.72,2391.11 4187.63,2391.11 4211.14,2367.6 4226.88,2367.6 C126.2@4232.28,2362.2 4238.19,2368.11 R117.1@4291.34,2368.11
NetC130_1: C130.1 U20.16 | length 80.6
  Top Layer w9.84: U20.16@3956.69,850.39 3956.69,856.1 3956.89,856.3 C130.1@4031.5,856.3
NetC130_2: C130.2 U20.1 | length 101.5
  Top Layer w9.84: U20.1@3982.29,875.98 4011.01,875.98 4012.05,877.03 4054.07,877.03 C130.2@4074.8,856.3
NetC131_1: C131.1 U20.2 | length 46.4
  Top Layer w9.84: U20.2@3989.18,895.71 4017.76,895.71 4027.56,905.51 C131.1@4031.5,905.51
NetC131_2: C131.2 U20.3 | length 105.6
  Top Layer w9.84: U20.3@3982.29,915.35 3982.48,915.55 4001.36,915.55 4012.05,926.24 4054.07,926.24 C131.2@4074.8,905.51
NetC132_1: C132.1 U20.15 | length 54.4
  Top Layer w9.84: U20.15@3937.01,850.39 3937.01,814.96 3944.88,807.09 C132.1@3952.76,807.09
NetC133_1: C133.1 U20.4 | length 57.4
  Top Layer w9.84: U20.4@3982.29,935.04 3996.06,935.04 4009.25,948.22 4024.99,948.22 C133.1@4031.5,954.72
NetC137_1: C137.1 R136.1 R137.2
NetC142_1: C142.1 R142.1 R143.2
NetC144_2: C144.2 D33.1 R146.2 TP53.1 U25.2 | length 428.4
  Top Layer w5.91: TP53.1@4330.71,1742.13 4281.5,1692.91 4281.5,1640.75 4317.91,1604.33 U25.2@4325.79,1604.33 4360.23,1604.33 4379.92,1624.02 4379.92,1673.22 4389.76,1683.07 D33.1@4448.48,1683.07 4448.48,1651.24 4429.13,1631.89 R146.2@4429.13,1627.95
NetC146_2: C146.2 D34.1 R150.2 TP55.1 U27.2 | length 409.2
  Top Layer w5.91: TP55.1@4320.87,1318.9 4421.26,1318.9 4446.85,1344.49 D34.1@4446.85,1377.95 ; U27.2@4325.79,1456.69 4360.24,1456.69 4379.93,1437.01 4379.93,1397.63 4399.61,1377.95 D34.1@4446.85,1377.95 ; R150.2@4429.13,1433.07 4429.13,1429.13 4446.85,1411.42 D34.1@4446.85,1377.95
NetC150_2: C150.2 R158.2 U29.96 | length 179.6
  Top Layer w9.84: R158.2@937.01,4669.29 942.91,4663.39 U29.96@1114.17,4663.39
NetC159_1: C159.1 C160.2 C161.1 U29.87 U29.115 | length 697.5
  Top Layer w9.84: C159.1@925.2,4316.93 929.13,4320.86 C160.2@984.26,4320.86 U29.115@1055.12,4320.87 1141.73,4320.87 1255.91,4435.04 U29.87@1255.91,4663.39 1255.91,4698.82 1291.34,4734.25 C161.1@1295.28,4734.25
NetC162_2: C162.2 R164.1 U29.68 | length 126.6
  Top Layer w7.87: U29.68@1555.12,4663.39 1555.12,4694.88 1570.87,4710.63 R164.1@1570.87,4783.46
NetC163_1: C163.1 U29.89 Y3.3 | length 252.4
  Top Layer w5.91: C163.1@1053.15,4809.06 1110.24,4809.06 Y3.3@1118.11,4801.18 1122.05,4801.18 1224.41,4698.82 U29.89@1224.41,4663.39
NetC164_1: C164.1 U29.88 Y3.1 | length 321.9
  Top Layer w5.91: U29.88@1240.16,4663.39 1240.16,4697.08 1161.42,4775.82 1161.42,4824.8 1200.79,4864.17 Y3.1@1204.72,4864.17 1261.81,4864.17 C164.1@1269.68,4856.3
NetD1_1: D1.1 D2.2 R1.1 | length 249.9
  Top Layer w5.91: D1.1@807.09,805.12 800.16,805.12 793.27,798.23 D2.2@793.27,758.92 795.74,756.45 847.88,756.45 875.98,728.35 875.98,669.29 885.83,659.45 R1.1@911.42,659.45
NetD2_1: D2.1 U1.4 | length 257.3
  Top Layer w5.91: D2.1@793.27,695.92 v1(835.07,695.92) ; v1(994.09,659.45) 993.98,659.57 993.98,678.03 997.05,681.1 1014.63,681.1 1015.82,679.92 1022.83,679.92 U1.4@1023.62,679.13
  Bottom Layer w5.91: v1@844.49,696.85 881.89,659.45 v1(994.09,659.45)
NetD3_2: D3.2 D4.1 | length 69.7
  Top Layer w5.91: D4.1@793.27,602.36 860.24,602.36 D3.2@862.2,600.39
NetD4_2: D4.2 R7.1 | length 53.1
  Top Layer w5.91: R7.1@797.24,486.22 D4.2@797.24,539.37
NetD5_1: D5.1 R13.1 | length 266.6
  Top Layer w5.91: D5.1@781.5,2224.41 783.46,2222.44 R13.1@783.46,1958.66
NetD6_1: D6.1 R19.1 | length 246.9
  Top Layer w5.91: R19.1@773.62,1033.46 773.62,1277.56 D6.1@775.59,1279.53
NetD7_2: D7.2 L6.2 U5.1 U5.24
NetD11_1: D11.1 L8.1 U5.13 U5.14
NetD13_1: D13.1 Q3.3@1732.28,2913.39 | length 66.9
  Top Layer w5.91: D13.1@1665.35,2913.39 Q3.3@1732.28,2913.39
NetD13_2: D13.2 R35.1 | length 84.2
  Top Layer w5.91: D13.2@1602.36,2913.39 1615.16,2926.18 1615.16,2934.06 1653.54,2972.44 R35.1@1657.48,2972.44
NetD17_1: D17.1 Q5.2@4027.56,4394.69 | length 59.7
  Top Layer w7.87: Q5.2@4027.56,4394.69 4054.13,4394.69 4074.8,4374.02 D17.1@4078.74,4374.02
NetD20_2: D20.2 R94.1 | length 54.4
  Top Layer w5.91: D20.2@4196.85,2838.58 4204.72,2846.46 R94.1@4248.03,2846.46
NetD22_2: D22.2 R96.2 | length 188
  Top Layer w5.91: D22.2@4196.85,2771.65 4208.66,2783.46 R96.2@4379.92,2783.46
NetD24_1: D24.1 R103.2 U15.3 | length 144.9
  Top Layer w5.91: U15.3@3508.86,3076.77 3513.78,3081.69 D24.1@3513.78,3139.76 3513.78,3167.32 3526.38,3179.92 R103.2@3560.9,3179.92
NetD25_2: D25.2 SW3.2 | length 415.5
  Top Layer w7.87: SW3.2@3454.72,2853.53 3490.74,2853.53 3530.18,2892.96 3681.84,2892.96 3728.35,2846.46 D25.2@3834.65,2846.46
NetD27_2: D27.2 R109.1 | length 53.1
  Top Layer w5.91: D27.2@3866.34,2144.47 R109.1@3919.49,2144.47
NetD28_1: D28.1 Q16.3@4173.23,2312.99 | length 490.1
  Top Layer w5.91: D28.1@3803.35,2075.57 v1(3833.78,2075.57) ; v1(4143.7,2263.78) 4143.7,2301.18 4155.51,2312.99 Q16.3@4173.23,2312.99
  Bottom Layer w5.91: v1(3833.78,2075.57) 3886.59,2075.57 4074.8,2263.78 v1(4143.7,2263.78)
NetD28_2: D28.2 R120.1 | length 53.1
  Top Layer w5.91: D28.2@3866.34,2075.57 R120.1@3919.49,2075.57
NetD38_2: D38.2 R159.1 | length 389.7
  Top Layer w7.87: D38.2@933.07,3927.17 895.67,3927.17 875.98,3946.85 875.98,4133.86 905.51,4163.39 952.76,4163.39 984.25,4131.89 R159.1@984.25,4127.95
NetD39_2: D39.2 R160.1 | length 185.6
  Top Layer w7.87: R160.1@925.2,4127.95 925.2,4124.02 895.67,4094.49 895.67,3996.06 905.51,3986.22 D39.2@933.07,3986.22
NetJ3_1: J3.1 U9.71 | length 733.1
  Top Layer w5.91: J3.1@2098.43,4824.41 2145.67,4777.17 2145.67,4645.67 2204.72,4586.61 2344.57,4586.61 2399.68,4531.5 2503.94,4531.5 2568.9,4596.46 U9.71@2568.9,4633.86
NetJ3_3: J3.3 U9.70 | length 609.7
  Top Layer w5.91: J3.3@2098.43,4624.41 2128.88,4593.96 2148.03,4574.8 2342.37,4574.8 2397.49,4519.69 2523.62,4519.69 2588.58,4584.65 U9.70@2588.58,4633.86
NetJ6_1: J6.1 R66.1 | length 108.5
  Top Layer w9.84: J6.1@4369.29,4133.86 4380.61,4145.18 4380.61,4181.8 4393.7,4194.89 R66.1@4393.7,4232.28
NetJ8_1: J8.1 R74.2 U12.2 | length 239.7
  Top Layer w9.84: U12.2@4301.18,3548.23 4301.32,3548.09 4301.32,3519.55 4313.58,3507.28 4342.13,3507.28 4360.87,3488.54 R74.2@4360.87,3447.09 4363.07,3444.88 J8.1@4457.09,3444.88
NetJ9_1: J9.1 R84.2 | length 226.6
  Top Layer w5.91: J9.1@3433.46,3759.84 3553.45,3639.86 R84.2@3553.45,3582.91
NetJ9_2: J9.2 Q8.3@4050.42,3769.69 R80.2 R81.2 | length 572.8
  Top Layer w7.87: J9.2@3533.46,3759.84 3573.88,3800.26 3709.58,3800.26 R80.2@3718.5,3791.34 3718.5,3792.07 3787.4,3792.07 3802.17,3806.83 4035.69,3806.83 4050.42,3792.1 Q8.3@4050.42,3769.69
NetJ9_3: J9.3 R83.2 | length 221.1
  Top Layer w7.87: J9.3@3633.46,3759.84 3633.65,3760.03 3819.08,3760.03 3838.58,3779.53 R83.2@3846.46,3779.53
NetJ12_1: J12.1 U16.7 | length 485.6
  Top Layer w5.91: v1(4389.76,2204.72) 4409.45,2224.41 4419.29,2224.41 U16.7@4421.26,2226.38
  Bottom Layer w5.91: J12.1@4075.59,1889.76 4075.59,1890.16 4389.76,2204.33 v1(4389.76,2204.72)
